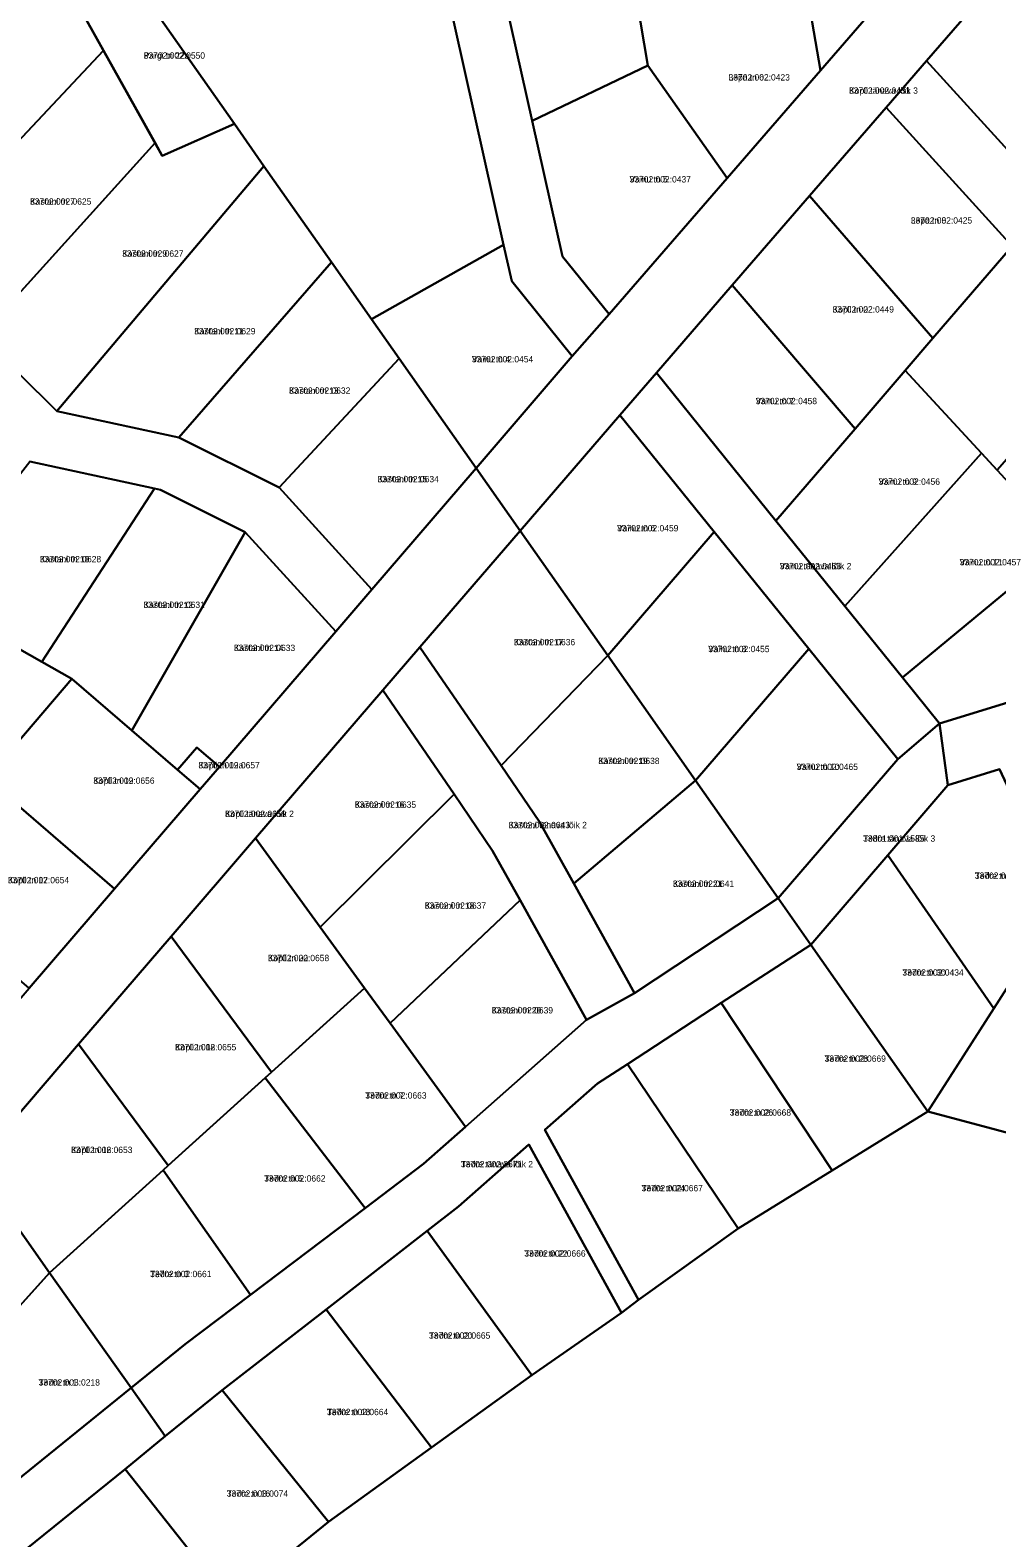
# Model space of a CAD drawing. Extents: x 551583 to 585220, y 6539942 to 6568852.
# Drawn here: x 567120.7 to 567349.4, y 6560564.2 to 6560920.6 of the extents above; entities that cross this region are included whole.
import ezdxf

# ---------------------------------------------------------------- set-up
doc = ezdxf.new("R2010")
doc.units = 0
for name, color, linetype in [('L_AADRESS', 7, 'Continuous'), ('PIIR', 7, 'Continuous'), ('TUNNUS', 7, 'Continuous')]:
    doc.layers.add(name, color=color, linetype=linetype)

msp = doc.modelspace()

# ---------------------------------------------------------------- linework, layer by layer
at = {"layer": 'PIIR'}
for points in [[(567133.73, 6560948.64), (567281.21, 6561019.08), (567284.54, 6561013.46), (567256.07, 6560999.86), (567230.81, 6560987.79), (567205.38, 6560975.65), (567211.31, 6560958.51), (567230.68, 6560938.35), (567239.44, 6560899.2), (567246.61, 6560867.12), (567257.65, 6560853.46), (567248.94, 6560843.56), (567234.59, 6560861.32), (567232.66, 6560869.91), (567218.75, 6560932.14), (567185.8, 6560966.3), (567137.53, 6560943.24)], [(567292.19, 6561000.54), (567315, 6561013.39), (567328.1, 6560991.51), (567352.13, 6560966.79), (567356.45, 6560962.35), (567349.32, 6560959.26), (567320.15, 6560989.07), (567309.97, 6560976), (567316.01, 6560940.61), (567329.82, 6560936.75), (567307.62, 6560911.14), (567303.59, 6560934.49), (567297.42, 6560970.23)], [(567226.17, 6560817.09), (567248.94, 6560843.56), (567257.65, 6560853.46), (567285.55, 6560885.65), (567307.62, 6560911.14), (567329.82, 6560936.75), (567349.32, 6560959.26), (567356.45, 6560962.35), (567362.74, 6560965.91), (567393.44, 6560983.31), (567402.65, 6560971.29), (567373.16, 6560954.58), (567363.84, 6560949.29), (567352.19, 6560935.85), (567332.74, 6560913.41), (567323.18, 6560902.37), (567305.06, 6560881.46), (567286.78, 6560860.36), (567268.82, 6560839.63), (567260.18, 6560829.65), (567236.58, 6560802.28)], [(567137.53, 6560943.24), (567185.8, 6560966.3), (567218.75, 6560932.14), (567232.66, 6560869.91), (567201.44, 6560852.28), (567191.94, 6560865.8), (567175.99, 6560888.5), (567168.99, 6560898.46)], [(567230.68, 6560938.35), (567250.01, 6560947.58), (567259.92, 6560952.32), (567264.18, 6560927.68), (567266.83, 6560912.28), (567239.44, 6560899.2)], [(567126.11, 6560937.17), (567137.53, 6560943.24), (567168.99, 6560898.46), (567151.94, 6560890.96)], [(567073.26, 6560883.48), (567126.11, 6560937.17), (567138.02, 6560915.86), (567091.08, 6560865.94)], [(567332.74, 6560913.41), (567352.19, 6560935.85), (567380.97, 6560902.77), (567360.8, 6560882.54)], [(567264.18, 6560927.68), (567303.59, 6560934.49), (567307.62, 6560911.14), (567285.55, 6560885.65), (567266.83, 6560912.28)], [(567091.08, 6560865.94), (567138.02, 6560915.86), (567150.25, 6560893.97), (567108.9, 6560848.4)], [(567239.44, 6560899.2), (567266.83, 6560912.28), (567285.55, 6560885.65), (567257.65, 6560853.46), (567246.61, 6560867.12)], [(567323.18, 6560902.37), (567332.74, 6560913.41), (567360.8, 6560882.54), (567382.03, 6560859.18), (567403.84, 6560835.19), (567426.27, 6560810.51), (567418.17, 6560797.86), (567396.89, 6560821.27), (567374.82, 6560845.56), (567352.97, 6560869.6)], [(567305.06, 6560881.46), (567323.18, 6560902.37), (567352.97, 6560869.6), (567334.26, 6560847.84)], [(567108.9, 6560848.4), (567150.25, 6560893.97), (567151.94, 6560890.96), (567168.99, 6560898.46), (567175.99, 6560888.5), (567127.03, 6560830.55)], [(567127.03, 6560830.55), (567175.99, 6560888.5), (567191.94, 6560865.8), (567155.89, 6560824.37)], [(567286.78, 6560860.36), (567305.06, 6560881.46), (567334.26, 6560847.84), (567327.66, 6560840.16), (567315.82, 6560826.38)], [(567201.44, 6560852.28), (567232.66, 6560869.91), (567234.59, 6560861.32), (567248.94, 6560843.56), (567226.17, 6560817.09), (567207.96, 6560843)], [(567327.66, 6560840.16), (567334.26, 6560847.84), (567352.97, 6560869.6), (567374.82, 6560845.56), (567349.42, 6560816.58), (567345.7, 6560820.61)], [(567155.89, 6560824.37), (567191.94, 6560865.8), (567201.44, 6560852.28), (567207.96, 6560843), (567179.55, 6560812.51)], [(567268.82, 6560839.63), (567286.78, 6560860.36), (567315.82, 6560826.38), (567297.12, 6560804.61)], [(567179.55, 6560812.51), (567207.96, 6560843), (567226.17, 6560817.09), (567201.51, 6560788.4)], [(567260.18, 6560829.65), (567268.82, 6560839.63), (567297.12, 6560804.61), (567313.41, 6560784.45), (567327.03, 6560767.59), (567335.82, 6560756.71), (567325.93, 6560748.27), (567304.87, 6560774.33), (567282.48, 6560802.04)], [(567297.12, 6560804.61), (567315.82, 6560826.38), (567327.66, 6560840.16), (567345.7, 6560820.61), (567313.41, 6560784.45)], [(567236.58, 6560802.28), (567260.18, 6560829.65), (567282.48, 6560802.04), (567257.31, 6560772.78)], [(567095.83, 6560786.9), (567120.61, 6560818.64), (567150.12, 6560812.31), (567123.42, 6560771.28)], [(567313.41, 6560784.45), (567345.7, 6560820.61), (567349.42, 6560816.58), (567365.39, 6560799.27), (567327.03, 6560767.59)], [(567096.98, 6560666.86), (567120.45, 6560694.15), (567140.67, 6560717.66), (567160.88, 6560741.16), (567165.44, 6560746.47), (567192.97, 6560778.47), (567201.51, 6560788.4), (567226.17, 6560817.09), (567236.58, 6560802.28), (567212.89, 6560774.8), (567204.12, 6560764.6), (567174, 6560729.58), (567154.06, 6560706.39), (567132.1, 6560680.86), (567107.4, 6560652.13)], [(567123.42, 6560771.28), (567150.12, 6560812.31), (567151.54, 6560812), (567171.57, 6560801.97), (567144.77, 6560755.02), (567130.55, 6560767.24)], [(567144.77, 6560755.02), (567171.57, 6560801.97), (567192.97, 6560778.47), (567165.44, 6560746.47), (567160.14, 6560751.03), (567155.57, 6560745.72)], [(567212.89, 6560774.8), (567236.58, 6560802.28), (567257.31, 6560772.78), (567232.08, 6560746.75)], [(567257.31, 6560772.78), (567282.48, 6560802.04), (567304.87, 6560774.33), (567278.07, 6560743.24)], [(567327.03, 6560767.59), (567365.39, 6560799.27), (567371.23, 6560792.94), (567389.46, 6560773.17), (567335.82, 6560756.71)], [(567077.03, 6560767.52), (567095.83, 6560786.9), (567123.42, 6560771.28), (567130.55, 6560767.24), (567110.34, 6560743.74), (567087.91, 6560756.57)], [(567349.96, 6560745.89), (567337.81, 6560742.16), (567335.82, 6560756.71), (567389.46, 6560773.17), (567405.52, 6560778.1), (567393.42, 6560759.22), (567367.86, 6560719.32), (567364.76, 6560714.47)], [(567204.12, 6560764.6), (567212.89, 6560774.8), (567232.08, 6560746.75), (567241.16, 6560733.48), (567249.28, 6560718.85), (567263.65, 6560692.95), (567252.28, 6560686.65), (567236.57, 6560714.97), (567230.09, 6560726.64), (567220.95, 6560740)], [(567232.08, 6560746.75), (567257.31, 6560772.78), (567278.07, 6560743.24), (567249.28, 6560718.85), (567241.16, 6560733.48)], [(567278.07, 6560743.24), (567304.87, 6560774.33), (567325.93, 6560748.27), (567297.64, 6560715.38)], [(567110.34, 6560743.74), (567130.55, 6560767.24), (567144.77, 6560755.02), (567155.57, 6560745.72), (567160.88, 6560741.16), (567140.67, 6560717.66)], [(567174, 6560729.58), (567204.12, 6560764.6), (567220.95, 6560740), (567189.3, 6560708.57)], [(567297.64, 6560715.38), (567325.93, 6560748.27), (567335.82, 6560756.71), (567337.81, 6560742.16), (567323.57, 6560725.6), (567305.35, 6560704.41)], [(567155.57, 6560745.72), (567160.14, 6560751.03), (567165.44, 6560746.47), (567160.88, 6560741.16)], [(567090.13, 6560720.23), (567110.34, 6560743.74), (567140.67, 6560717.66), (567120.45, 6560694.15)], [(567249.28, 6560718.85), (567278.07, 6560743.24), (567297.64, 6560715.38), (567263.65, 6560692.95)], [(567323.57, 6560725.6), (567337.81, 6560742.16), (567349.96, 6560745.89), (567364.76, 6560714.47), (567348.68, 6560689.36)], [(567189.3, 6560708.57), (567220.95, 6560740), (567230.09, 6560726.64), (567236.57, 6560714.97), (567205.85, 6560685.83), (567199.78, 6560694.16)], [(567154.06, 6560706.39), (567174, 6560729.58), (567189.3, 6560708.57), (567199.78, 6560694.16), (567177.79, 6560674.3)], [(567305.35, 6560704.41), (567323.57, 6560725.6), (567348.68, 6560689.36), (567333.06, 6560664.98)], [(567144.54, 6560599.63), (567157.35, 6560609.96), (567172.84, 6560621.67), (567199.96, 6560642.16), (567213.77, 6560652.6), (567223.66, 6560661.35), (567252.28, 6560686.65), (567263.65, 6560692.95), (567297.64, 6560715.38), (567305.35, 6560704.41), (567284.18, 6560690.65), (567261.97, 6560676.2), (567254.88, 6560671.59), (567242.46, 6560660.61), (567264.59, 6560620.44), (567260.55, 6560617.35), (567238.62, 6560657.21), (567222.01, 6560642.53), (567214.62, 6560636.78), (567190.71, 6560618.18), (567166.14, 6560599.07), (567152.65, 6560588.18)], [(567205.85, 6560685.83), (567236.57, 6560714.97), (567252.28, 6560686.65), (567223.66, 6560661.35)], [(567132.1, 6560680.86), (567154.06, 6560706.39), (567177.79, 6560674.3), (567176.27, 6560672.93), (567153.34, 6560652.22)], [(567284.18, 6560690.65), (567305.35, 6560704.41), (567333.06, 6560664.98), (567310.38, 6560651.05)], [(567176.27, 6560672.93), (567177.79, 6560674.3), (567199.78, 6560694.16), (567205.85, 6560685.83), (567223.66, 6560661.35), (567213.77, 6560652.6), (567199.96, 6560642.16)], [(567261.97, 6560676.2), (567284.18, 6560690.65), (567310.38, 6560651.05), (567288.18, 6560637.35)], [(567107.4, 6560652.13), (567132.1, 6560680.86), (567153.34, 6560652.22), (567152.14, 6560651.14), (567125.27, 6560626.87)], [(567242.46, 6560660.61), (567254.88, 6560671.59), (567261.97, 6560676.2), (567288.18, 6560637.35), (567264.59, 6560620.44)], [(567152.14, 6560651.14), (567153.34, 6560652.22), (567176.27, 6560672.93), (567199.96, 6560642.16), (567172.84, 6560621.67)], [(567175.79, 6560555.46), (567191.26, 6560567.94), (567215.62, 6560585.51), (567239.34, 6560602.61), (567260.55, 6560617.35), (567264.59, 6560620.44), (567288.18, 6560637.35), (567310.38, 6560651.05), (567333.06, 6560664.98), (567707.85, 6560564.95), (567505.71, 6560510.77), (567305.7, 6560457.16), (567295.8, 6560454.51)], [(567214.62, 6560636.78), (567222.01, 6560642.53), (567238.62, 6560657.21), (567260.55, 6560617.35), (567239.34, 6560602.61)], [(567080.74, 6560619.66), (567088.5, 6560630.15), (567107.4, 6560652.13), (567125.27, 6560626.87), (567097.1, 6560595.63), (567084.91, 6560613.53)], [(567125.27, 6560626.87), (567152.14, 6560651.14), (567172.84, 6560621.67), (567157.35, 6560609.96), (567144.54, 6560599.63)], [(567190.71, 6560618.18), (567214.62, 6560636.78), (567239.34, 6560602.61), (567215.62, 6560585.51)], [(567097.1, 6560595.63), (567125.27, 6560626.87), (567144.54, 6560599.63), (567112.16, 6560573.48)], [(567166.14, 6560599.07), (567190.71, 6560618.18), (567215.62, 6560585.51), (567191.26, 6560567.94)], [(567152.65, 6560588.18), (567166.14, 6560599.07), (567191.26, 6560567.94), (567175.79, 6560555.46), (567167.91, 6560549.1), (567143.12, 6560580.44)], [(567119.8, 6560561.56), (567143.12, 6560580.44), (567167.91, 6560549.1), (567144.56, 6560530.26)]]:
    msp.add_lwpolyline(points, close=True, dxfattribs=at)
for points in [[(567108.9, 6560848.4), (567127.03, 6560830.55), (567155.89, 6560824.37), (567179.55, 6560812.51), (567201.51, 6560788.4), (567192.97, 6560778.47), (567171.57, 6560801.97), (567151.54, 6560812), (567150.12, 6560812.31), (567120.61, 6560818.64)], [(567707.85, 6560564.95), (567333.06, 6560664.98), (567348.68, 6560689.36), (567364.76, 6560714.47)], [(567082.27, 6560549.35), (567112.16, 6560573.48), (567144.54, 6560599.63), (567152.65, 6560588.18), (567143.12, 6560580.44), (567119.8, 6560561.56)]]:
    msp.add_lwpolyline(points, dxfattribs=at)

# ---------------------------------------------------------------- texts
at = {"layer": 'L_AADRESS'}
for s, p in [('Pargi tn 22a', (567147.55, 6560913.9)), ('Lepa tn 6', (567285.9, 6560908.74)), ('Kopli tänava lõik 3', (567314.41, 6560905.61)), ('Vainu tn 5', (567262.49, 6560884.63)), ('Kastani tn 7', (567120.66, 6560879.38)), ('Lepa tn 8', (567329.02, 6560874.92)), ('Kastani tn 9', (567142.45, 6560867.08)), ('Kopli tn 22', (567310.52, 6560853.88)), ('Kastani tn 11', (567159.48, 6560848.73)), ('Vainu tn 4', (567225.19, 6560842.09)), ('Kastani tn 13', (567181.93, 6560834.67)), ('Vainu tn 7', (567292.32, 6560832.21)), ('Kastani tn 15', (567202.86, 6560813.75)), ('Vainu tn 9', (567321.41, 6560813.15)), ('Vainu tn 6', (567259.53, 6560802.13)), ('Kastani tn 10', (567122.97, 6560794.83)), ('Vainu tänava lõik 2', (567298, 6560793.18)), ('Vainu tn 11', (567340.58, 6560794.1)), ('Kastani tn 12', (567147.5, 6560784.03)), ('Kastani tn 14', (567168.87, 6560773.85)), ('Kastani tn 17', (567235.1, 6560775.21)), ('Vainu tn 8', (567281.09, 6560773.58)), ('Kopli tn 19a', (567160.5, 6560746.1)), ('Kastani tn 19', (567255.07, 6560747.12)), ('Vainu tn 10', (567302, 6560745.72)), ('Kopli tn 19', (567135.61, 6560742.45)), ('Kopli tänava lõik 2', (567166.78, 6560734.61)), ('Kastani tn 16', (567197.48, 6560736.78)), ('Kastani tänava lõik 2', (567233.88, 6560731.96)), ('Tedre tänava lõik 3', (567317.73, 6560728.77)), ('Tedre tn 32', (567344.16, 6560719.99)), ('Kopli tn 17', (567115.4, 6560718.94)), ('Kastani tn 21', (567272.72, 6560718.09)), ('Kastani tn 18', (567214.04, 6560712.91)), ('Kopli tn 20', (567176.92, 6560700.52)), ('Tedre tn 30', (567327.02, 6560697.1)), ('Kastani tn 20', (567229.87, 6560688.16)), ('Kopli tn 18', (567154.95, 6560679.43)), ('Tedre tn 28', (567308.62, 6560676.73)), ('Tedre tn 7', (567199.96, 6560668.03)), ('Tedre tn 26', (567286.18, 6560663.98)), ('Kopli tn 16', (567130.37, 6560655.16)), ('Tedre tänava lõik 2', (567222.58, 6560651.78)), ('Tedre tn 5', (567176.05, 6560648.41)), ('Tedre tn 24', (567265.32, 6560646.1)), ('Tedre tn 22', (567237.58, 6560630.67)), ('Tedre tn 3', (567149.06, 6560625.81)), ('Tedre tn 20', (567215.03, 6560611.26)), ('Tedre tn 1', (567122.68, 6560600.18)), ('Tedre tn 18', (567190.88, 6560593.18)), ('Tedre tn 16', (567167.19, 6560573.89))]:
    msp.add_text(s, height=1.5, dxfattribs=at).set_placement(p)
at = {"layer": 'TUNNUS'}
for s, p in [('33702:002:0550', (567147.55, 6560913.9)), ('33702:002:0423', (567285.9, 6560908.74)), ('33702:002:0431', (567314.41, 6560905.61)), ('33702:002:0437', (567262.49, 6560884.63)), ('33702:002:0625', (567120.66, 6560879.38)), ('33702:002:0425', (567329.02, 6560874.92)), ('33702:002:0627', (567142.45, 6560867.08)), ('33702:002:0449', (567310.52, 6560853.88)), ('33702:002:0629', (567159.48, 6560848.73)), ('33702:002:0454', (567225.19, 6560842.09)), ('33702:002:0632', (567181.93, 6560834.67)), ('33702:002:0458', (567292.32, 6560832.21)), ('33702:002:0634', (567202.86, 6560813.75)), ('33702:002:0456', (567321.41, 6560813.15)), ('33702:002:0459', (567259.53, 6560802.13)), ('33702:002:0628', (567122.97, 6560794.83)), ('33702:002:0453', (567298, 6560793.18)), ('33702:002:0457', (567340.58, 6560794.1)), ('33702:002:0631', (567147.5, 6560784.03)), ('33702:002:0633', (567168.87, 6560773.85)), ('33702:002:0636', (567235.1, 6560775.21)), ('33702:002:0455', (567281.09, 6560773.58)), ('33702:002:0657', (567160.5, 6560746.1)), ('33702:002:0638', (567255.07, 6560747.12)), ('33702:002:0465', (567302, 6560745.72)), ('33702:002:0656', (567135.61, 6560742.45)), ('33702:002:0659', (567166.78, 6560734.61)), ('33702:002:0635', (567197.48, 6560736.78)), ('33702:002:0643', (567233.88, 6560731.96)), ('33801:001:1585', (567317.73, 6560728.77)), ('33702:002:0451', (567344.16, 6560719.99)), ('33702:002:0654', (567115.4, 6560718.94)), ('33702:002:0641', (567272.72, 6560718.09)), ('33702:002:0637', (567214.04, 6560712.91)), ('33702:002:0658', (567176.92, 6560700.52)), ('33702:002:0434', (567327.02, 6560697.1)), ('33702:002:0639', (567229.87, 6560688.16)), ('33702:002:0655', (567154.95, 6560679.43)), ('33702:002:0669', (567308.62, 6560676.73)), ('33702:002:0663', (567199.96, 6560668.03)), ('33702:002:0668', (567286.18, 6560663.98)), ('33702:002:0653', (567130.37, 6560655.16)), ('33702:002:0671', (567222.58, 6560651.78)), ('33702:002:0662', (567176.05, 6560648.41)), ('33702:002:0667', (567265.32, 6560646.1)), ('33702:002:0666', (567237.58, 6560630.67)), ('33702:002:0661', (567149.06, 6560625.81)), ('33702:002:0665', (567215.03, 6560611.26)), ('33702:003:0218', (567122.68, 6560600.18)), ('33702:002:0664', (567190.88, 6560593.18)), ('33702:003:0074', (567167.19, 6560573.89))]:
    msp.add_text(s, height=1.5, dxfattribs=at).set_placement(p)

doc.saveas('drawing.dxf')
